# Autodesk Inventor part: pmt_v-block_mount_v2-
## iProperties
Shininess: 64.0
Length Units: 11269
Angle Units: 11279
Time Units: 11290
Mass Units: 11283
Length Display Precision: 3
Angle Display Precision: 2
Compacted: True
Part Number: pmt_v-block_mount_v2-
Document SubType Name: Modeling
Created: 2004-08
Designer: John Blackburn
Manufacturer: Standard
Standards Organization: Custom
Density: 0.0
Volumn: 0.0
Area: 0.0
PropertySet Name: Model Information
Control State: 0
Master: False
Checked Out: False
Author: John Blackburn
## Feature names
1. Extrusion1
2. Hole1
3. Hole2
4. Hole3
